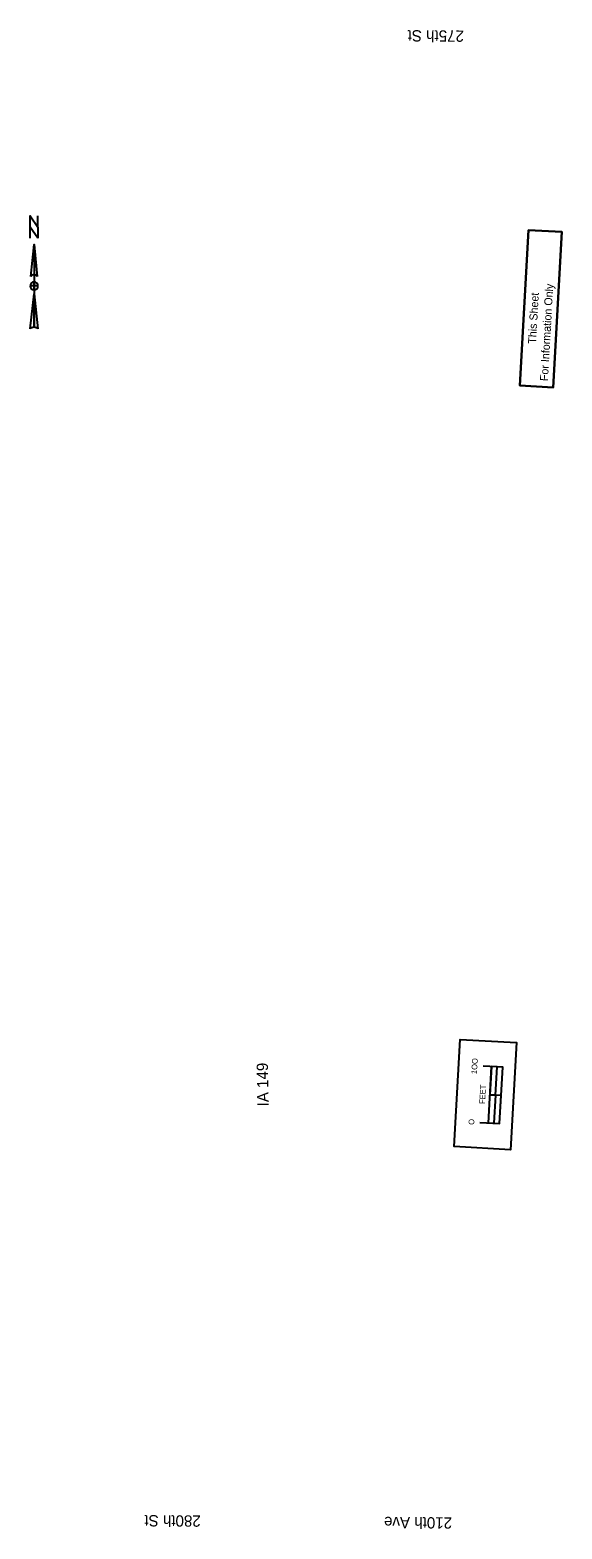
# Model space of a CAD drawing. Extents: x 23417754 to 23421386, y 6737896 to 6790956.
# Drawn here: x 23420374 to 23421315, y 6764633 to 6767288 of the extents above; entities that cross this region are included whole.
import ezdxf

# ---------------------------------------------------------------- set-up
doc = ezdxf.new("R2010")
doc.units = 0
for name, color, linetype in [('Curb', 7, 'Continuous'), ('Default', 7, 'Continuous'), ('RasterAttachment', 7, 'Continuous')]:
    doc.layers.add(name, color=color, linetype=linetype)

msp = doc.modelspace()

# ---------------------------------------------------------------- linework, layer by layer
at = {"layer": 'Curb'}
for p, q in [((23420380.9, 6766907.7), (23420386.5, 6766851.3)), ((23420380.9, 6766907.7), (23420380.9, 6766761.2)), ((23420375.2, 6766851.3), (23420375.2, 6766851.3)), ((23420375.4, 6766851.9), (23420376.5, 6766853)), ((23420373.8, 6766758.4), (23420380.9, 6766820.4)), ((23420380.9, 6766827.4), (23420380.9, 6766827.4)), ((23421207.4, 6765400.8), (23421187.4, 6765401.9)), ((23421207.4, 6765400.8), (23421187.4, 6765401.9))]:
    msp.add_line(p, q, dxfattribs=at)
for points in [[(23420387.9, 6766919), (23420373.8, 6766938.7), (23420373.8, 6766958.4), (23420387.9, 6766938.7)], [(23421240.5, 6766658.1), (23421255.9, 6766933.3), (23421314.9, 6766930), (23421299.5, 6766654.8)], [(23421299.5, 6766654.8), (23421314.9, 6766930), (23421255.9, 6766933.3), (23421240.5, 6766658.1)], [(23421124.2, 6765310.3), (23421134.8, 6765500), (23421234.6, 6765494.4), (23421224, 6765304.7)], [(23421224, 6765304.7), (23421124.2, 6765310.3), (23421134.8, 6765500), (23421234.6, 6765494.4)], [(23421197.3, 6765401.4), (23421200.1, 6765451.3), (23421190.2, 6765451.9), (23421187.4, 6765401.9)], [(23421204.6, 6765350.9), (23421207.4, 6765400.8), (23421197.3, 6765401.4), (23421194.5, 6765351.5)]]:
    msp.add_lwpolyline(points, close=True, dxfattribs=at)
for points in [[(23420373.8, 6766919), (23420373.8, 6766958.4), (23420387.9, 6766938.7), (23420387.9, 6766958.4)], [(23420375.2, 6766851.3), (23420380.9, 6766907.7), (23420380.9, 6766854.2)], [(23420380.9, 6766827.4), (23420380.9, 6766834.4), (23420373.8, 6766834.4)], [(23420387.9, 6766834.4), (23420380.9, 6766834.4), (23420380.9, 6766841.5)], [(23420380.9, 6766761.2), (23420380.9, 6766820.4), (23420387.9, 6766758.4)], [(23421169.6, 6765352.9), (23421204.6, 6765350.9), (23421210.2, 6765450.7), (23421175.2, 6765452.7)], [(23421184.6, 6765352), (23421190.2, 6765451.9)]]:
    msp.add_lwpolyline(points, dxfattribs=at)
for centre, radius, start, end in [((23420380.9, 6766834.4), 7.04, 90, 180), ((23420380.9, 6766834.4), 7.04, 180, 270), ((23420380.9, 6766847.1), 7.04, 90.0204, 143.1257), ((23420380.9, 6766847.1), 7.04, 36.8481, 90.0218), ((23420380.9, 6766834.4), 7.04, 0, 90), ((23420380.9, 6766834.4), 7.04, 270, 360), ((23420380.9, 6766751), 10.2, 89.9894, 133.619), ((23420380.9, 6766751), 10.2, 46.4021, 90.0006)]:
    msp.add_arc(centre, radius, start, end, dxfattribs=at)

# ---------------------------------------------------------------- texts
for s, height, p in [('For Information Only', 14.174, (23421290, 6766665.5)), ('This Sheet', 14.17, (23421268.9, 6766731.7)), ('1OO', 10, (23421164.4, 6765438.4)), ('1OO', 10, (23421164.4, 6765438.4)), ('FEET', 10, (23421178.5, 6765385.5)), ('O', 10, (23421159.4, 6765348.5)), ('O', 10, (23421159.4, 6765348.5))]:
    msp.add_text(s, height=height, rotation=86.8004, dxfattribs=at).set_placement(p)
at = {"layer": 'Default'}
msp.add_text('IA 149', height=20, rotation=90.9188, dxfattribs=at).set_placement((23420795.9, 6765381.6))
at = {"layer": 'RasterAttachment'}
for s, p in [('275th St', (23421141.5, 6767286.7)), ('280th St', (23420675.9, 6764657)), ('210th Ave', (23421120.5, 6764653.7))]:
    msp.add_text(s, height=20, rotation=179.5786, dxfattribs=at).set_placement(p)

doc.saveas('drawing.dxf')
